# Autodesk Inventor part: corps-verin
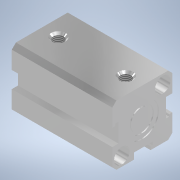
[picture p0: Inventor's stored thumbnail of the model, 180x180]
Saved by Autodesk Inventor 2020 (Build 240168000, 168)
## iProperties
Created: 2023-10
Part Number: corps-verin
Material: Aluminium 6061
Document SubType Name: Modeling
Designer: bruno
Density: 2.7 g/cm^3
Appearance: Aluminium - Plat
Author: bruno
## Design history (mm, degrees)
sketch "Esquisse1"
  geometry: L1 (0, 0)-(29, 0); L2 (29, 0)-(29, -29); L3 (10.5, -29)-(10.5, -27.5); L4 (18.5, -27)-(18.5, -29); L5 (10.5, -27.5)-(9.454, -27.5); L6 (9.454, -27.5)-(9.454, -26); L7 (9.454, -26)-(18.5, -26); L8 (18.5, -26)-(18.5, -27); L9 (0, -29)-(29, 0); L10 (0, -18.5)-(1.5, -18.5); L11 (2, -10.5)-(0, -10.5); L12 (1.5, -18.5)-(1.5, -19.546); L13 (1.5, -19.546)-(3, -19.546); L14 (3, -19.546)-(3, -10.5); L15 (3, -10.5)-(2, -10.5); L16 (0, 0)-(29, -29); L17 (29, -29)-(18.5, -29); L18 (10.5, -29)-(0, -29); L19 (0, -29)-(0, -18.5); L20 (0, -10.5)-(0, 0); L21 (19.546, -1.5)-(19.546, -3); L22 (18.5, -1.5)-(19.546, -1.5); L23 (18.5, 0)-(18.5, -1.5); L24 (19.546, -3)-(10.5, -3); L25 (10.5, -3)-(10.5, -2); L26 (10.5, -2)-(10.5, 0); C1 r 2 at (24.404, -24.404); C2 r 2 at (4.605, -4.605); 2 further points
  constraints: 52 end point, 14 symmetric about line, 7 parallel, 2 centre point, 2 horizontal, 2 perpendicular, 2 point on line
  dimensions: "d0" = 29 distance of L2.end L9.start; "d1" = 29 distance of L1.end L2.end; "d2" = 10.5 distance between parallel lines of L2 L4; "d6" = 1.5 distance between parallel lines of L18 L5; "d7" = 1.5 distance of L5.end L6.end; "d8" = 4 diameter of C1; "d9" = 4 diameter of C2; "d10" = 28 distance of C2.centre C1.centre; "d11" = 6.5 distance of L2.end C1.centre
extrude "Extrusion1" new body sketch "Esquisse1" distance "d12" = 48.5; taper "d13" = 0 deg
chamfer "Chanfrein1" distance "d14" = 2; stored, may be unused: second distance "d15" = 2, angle "d16" = 45 deg
sketch "Esquisse2"
  geometry: L1 (2, 29)-(0, 27) reference; L2 (1, 28)-(28, 1); L3 (27, 0)-(29, 2) reference; C1 r 8 at (14.5, 14.5); 1 further point
  constraints: 3 midpoint, 2 end point, 1 centre point
  dimensions: "d17" = 16 diameter of C1
extrude "Extrusion2" cut sketch "Esquisse2" distance "d18" = 0.5; taper "d19" = 0 deg
sketch "Esquisse3"
  geometry: C1 r 6 at (0, 0); C2 r 5 at (0, 0); 1 further point
  constraints: 2 centre point, 1 coincident
  dimensions: "d20" = 12 diameter of C1; "d21" = 10 diameter of C2
extrude "Extrusion3" cut sketch "Esquisse3" distance "d22" = 0.5; taper "d23" = 0 deg
sketch "Esquisse4"
  geometry: C1 r 2 at (4.605, 4.605) reference; C2 r 2 at (24.404, 24.404) reference; C3 r 3.75 at (24.404, 24.404); C4 r 3.75 at (4.605, 4.605); 1 further point
  constraints: 2 centre point, 2 coincident
  dimensions: "d24" = 7.5 diameter of C3; "d25" = 7.5 diameter of C4
extrude "Extrusion4" cut sketch "Esquisse4" distance "d26" = 6; taper "d27" = 0 deg
sketch "Esquisse5"
  geometry: C1 r 2 at (-24.404, 24.404) reference; C2 r 2 at (-4.605, 4.605) reference; C3 r 3.75 at (-24.404, 24.404) reference; C4 r 3.75 at (-4.605, 4.605) reference; C5 r 2.5 at (-24, 24.12) reference; C6 r 2.5 at (-5, 5) reference; 1 further point
extrude "Extrusion5" cut sketch "Esquisse5" distance "d28" = 6; taper "d29" = 0 deg
sketch "Esquisse6"
  geometry: L1 (-29, 27)-(-27, 29) reference; L2 (0, 2)-(-2, 0) reference; L3 (-28, 28)-(-1, 1); L4 (-2, 0)-(0, 2) reference; C1 r 9 at (-14.5, 14.5); C2 r 5.5 at (-14.5, 14.5); 1 further point
  constraints: 2 centre point, 2 end point, 2 midpoint, 1 coincident
  dimensions: "d30" = 18 diameter of C1; "d31" = 11 diameter of C2
extrude "Extrusion6" cut sketch "Esquisse6" distance "d32" = 4; taper "d33" = 0 deg
sketch "Esquisse7"
  geometry: C1 r 5.5 at (0, 0) reference; 1 further point
extrude "Extrusion7" join sketch "Esquisse7" distance "d34" = 2; taper "d35" = 0 deg
fillet "Congé1" dims "d36" = 0.5
chamfer "Chanfrein2" distance "d37" = 0.5; stored, may be unused: second distance "d38" = 2, angle "d39" = 45 deg
sketch "Esquisse8"
  geometry: C1 r 5 at (0, 0) reference; C2 r 3 at (0, 0); 1 further point
  constraints: 1 centre point, 1 coincident
  dimensions: "d40" = 6 diameter of C2
extrude "Extrusion8" cut sketch "Esquisse8" distance "d41" = 40; taper "d42" = 0 deg
sketch "Esquisse9"
  geometry: L1 (0, 25)-(0, 0) reference; L2 (48.5, 25)-(48.5, 0) reference; C1 r 2.5 at (8, 12.5); C2 r 2.5 at (40.5, 12.5); 1 further point
  constraints: 2 centre point
  dimensions: "d43" = 5 diameter of C1; "d44" = 8 distance from line of L1 C1.centre; "d45" = 5 diameter of C2; "d46" = 8 distance from line of C2.centre L2
extrude "Extrusion9" cut sketch "Esquisse9" distance "d47" = 10; taper "d48" = 0 deg
chamfer "Chanfrein3" distance "d49" = 1; stored, may be unused: second distance "d50" = 2, angle "d51" = 45 deg
feature "Filetage1" dims "d52" = 9, "d53" = 0
feature "Filetage2" dims "d54" = 9, "d55" = 0
feature "Filetage3" dims "d56" = 36.5, "d57" = 0
feature "Filetage4" dims "d58" = 36.5, "d59" = 0
node "Solide1"
node "Boucle projetée1"
node "Référence1"
node "Référence2"
other parameters: "d3" = 10.5, "d4" = 2
